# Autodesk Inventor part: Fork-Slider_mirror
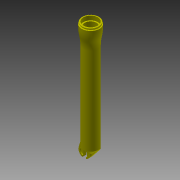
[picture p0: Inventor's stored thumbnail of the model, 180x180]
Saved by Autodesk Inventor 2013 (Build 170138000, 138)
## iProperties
Shininess: 64.0
Length Units: 11272
Angle Units: 11279
Time Units: 11290
Mass Units: 11286
Length Display Precision: 3
Angle Display Precision: 2
Compacted: True
Part Number: Fork-Slider_mirror
Document SubType Name: Modeling
Created: 2003-10
Designer: Autodesk, Inc.
Material: Generic
Manufacturer: Standard
Standards Organization: Custom
Mass: 115.052 g
Surface Area: 625.893 cm^2
Volume: 115.052 cm^3
Density: 1 g/cm^3
Density: 0.0
Volumn: 0.0
Area: 0.0
PropertySet Name: Model Information
Control State: 0
Master: False
Checked Out: False
Author: Autodesk, Inc.
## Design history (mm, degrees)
derived "Fork-Slider.ipt"
  workplane "Work Plane3"
  node "WorkPlane4"
  workplane "Work Plane8"
  node "WorkPlane5"
  node "WorkPlane1"
  node "WorkPlane2"
  node "WorkPlane3"
  node "WorkAxis1"
body "Solid1"
tag "TaggingFeature2"
workplane "Work Plane10"
workplane "Work Plane11"
workplane "Work Plane5"
workplane "Work Plane6"
feature "DerivedBody::Fork-Slider.ipt"
